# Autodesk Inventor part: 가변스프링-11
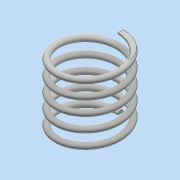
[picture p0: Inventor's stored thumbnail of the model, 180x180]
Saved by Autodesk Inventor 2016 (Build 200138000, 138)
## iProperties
Created: 2015-11
Part Number: 가변스프링-11
Material: 일반
Document SubType Name: Modeling
Designer: Administrator
Density: 1 g/cm^3
Appearance: 기본값
Mass: 1.06779 g
Surface Area: 21.6566 cm^2
Volume: 1.06779 cm^3
Author: Administrator
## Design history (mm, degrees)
sketch "스케치2"
  geometry: L1 (0, 0)-(11, 0); L2 (11, 0)-(11, 25.508); L3 (11, 25.508)-(0, 25.508); L4 (0, 25.508)-(0, 0); C1 r 1 at (11, 0)
  constraints: 8 end point, 2 parallel, 1 centre point, 1 coincident, 1 horizontal, 1 perpendicular
  dimensions: "d0" = 2 diameter of C1; "d1" = 22 diameter of L2 L4; "d2" = 25.50829 distance between parallel lines of L3 L1 (derived)
feature "코일1" sketch "스케치2" pitch "d3" = 10; turns "d5" = 5; dims "d4" = 25.50829 (= d2), "d6" = 0, angle "d7" = 90 deg, angle "d8" = 90 deg, "d9" = 0, "d10" = 0
sketch "스케치3"
  geometry: L1 (0, 12)-(0, 10) reference; 1 further point
  constraints: 1 vertical alignment
extrude "돌출1" cut sketch "스케치3" distance "d11" = 10; taper "d12" = 0 deg
node "작업 평면1"
sketch "스케치4"
  geometry: L1 (0, -1)-(0, 1) reference; 1 further point
  constraints: 1 vertical alignment
extrude "돌출2" cut sketch "스케치4" distance "d13" = 10; taper "d14" = 0 deg
node "솔리드1"
node "절단 모서리 투영1"
node "절단 모서리 투영2"
